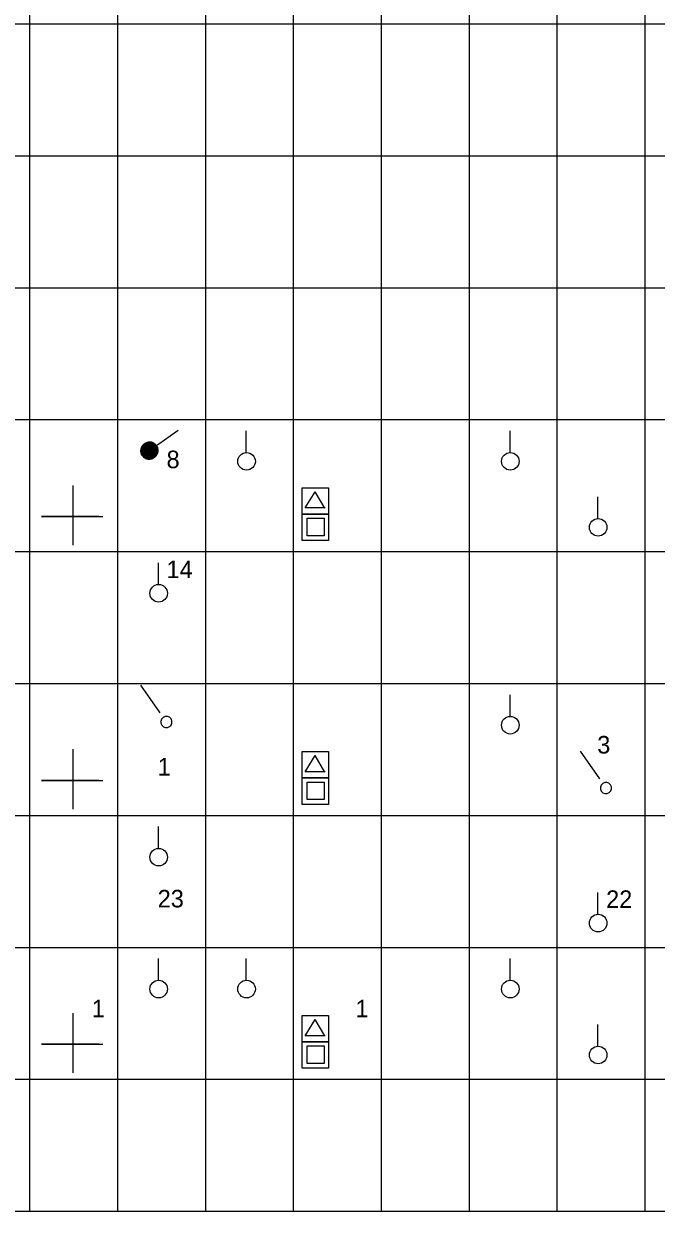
# Model space of a CAD drawing. Extents: x -28 to 822, y 61 to 665.
# Drawn here: x 192.5 to 264.4, y 111.7 to 246.8 of the extents above; entities that cross this region are included whole.
import ezdxf

# ---------------------------------------------------------------- set-up
doc = ezdxf.new("R2010")
doc.units = 0

# ---------------------------------------------------------------- blocks, each defined once
blk = doc.blocks.new('_X10')
for p, q in [((370.45, 480.11), (371.52, 481.17)), ((370.45, 480.13), (371.5, 481.17)), ((370.45, 480.14), (371.48, 481.17)), ((370.45, 480.16), (371.46, 481.17)), ((370.45, 480.18), (371.45, 481.17)), ((370.45, 480.2), (371.43, 481.17)), ((370.45, 480.21), (371.41, 481.17)), ((370.45, 480.23), (371.39, 481.17)), ((370.46, 480.06), (371.56, 481.17)), ((370.46, 480.08), (371.55, 481.17)), ((370.46, 480.09), (371.53, 481.17)), ((370.46, 480.25), (371.37, 481.17)), ((370.46, 480.27), (371.35, 481.17)), ((370.46, 480.29), (371.33, 481.17)), ((370.46, 480.01), (371.61, 481.16)), ((370.46, 480.03), (371.6, 481.16)), ((370.46, 480.04), (371.58, 481.16)), ((370.46, 480.31), (371.31, 481.16)), ((370.46, 480.33), (371.29, 481.16)), ((370.47, 480), (371.63, 481.16)), ((370.47, 480.35), (371.27, 481.16)), ((370.47, 479.97), (371.66, 481.15)), ((370.47, 479.98), (371.64, 481.15)), ((370.47, 480.37), (371.25, 481.15)), ((370.48, 479.95), (371.67, 481.15)), ((370.48, 480.4), (371.23, 481.15)), ((370.48, 479.93), (371.7, 481.14)), ((370.48, 479.94), (371.68, 481.14)), ((370.48, 480.42), (371.2, 481.14)), ((370.49, 479.91), (371.71, 481.14)), ((370.49, 479.88), (371.74, 481.13)), ((370.49, 479.9), (371.73, 481.13)), ((370.49, 480.45), (371.18, 481.13)), ((370.5, 479.87), (371.75, 481.13)), ((370.5, 480.47), (371.15, 481.13)), ((370.5, 479.86), (371.77, 481.12)), ((370.51, 479.84), (371.78, 481.12)), ((370.51, 480.5), (371.13, 481.12)), ((370.51, 479.83), (371.79, 481.11)), ((370.52, 479.82), (371.81, 481.11)), ((370.52, 480.52), (371.1, 481.11)), ((370.52, 479.81), (371.82, 481.1)), ((370.53, 479.79), (371.83, 481.1)), ((370.53, 480.55), (371.07, 481.1)), ((370.53, 479.78), (371.84, 481.09)), ((370.54, 479.77), (371.86, 481.09)), ((370.54, 479.76), (371.87, 481.08)), ((370.54, 480.58), (371.04, 481.08)), ((370.55, 479.74), (371.88, 481.08)), ((370.55, 479.73), (371.89, 481.07)), ((370.56, 480.62), (371.01, 481.07)), ((370.56, 479.72), (371.9, 481.06)), ((370.57, 479.71), (371.92, 481.06)), ((370.57, 479.7), (371.93, 481.05)), ((370.58, 479.69), (371.94, 481.05)), ((370.58, 480.66), (370.97, 481.05)), ((370.59, 479.67), (371.95, 481.04)), ((370.59, 479.66), (371.96, 481.03)), ((370.6, 479.65), (371.97, 481.03)), ((370.6, 479.64), (371.98, 481.02)), ((370.6, 480.7), (370.93, 481.02)), ((370.61, 479.63), (371.99, 481.01)), ((370.62, 479.62), (372, 481.01)), ((370.63, 479.61), (372.02, 481)), ((370.63, 479.6), (372.03, 480.99)), ((370.64, 480.75), (370.87, 480.99)), ((370.64, 479.59), (372.04, 480.98)), ((370.65, 479.58), (372.05, 480.98)), ((370.66, 479.57), (372.06, 480.97)), ((370.66, 479.56), (372.07, 480.96)), ((370.67, 479.55), (372.08, 480.95)), ((370.68, 479.54), (372.09, 480.95)), ((370.69, 479.53), (372.1, 480.94)), ((370.7, 479.52), (372.11, 480.93)), ((370.7, 479.51), (372.11, 480.92)), ((370.71, 480.84), (370.79, 480.92)), ((370.71, 479.5), (372.12, 480.91)), ((370.72, 479.49), (372.13, 480.9)), ((370.73, 479.48), (372.14, 480.9)), ((370.74, 479.47), (372.15, 480.89)), ((370.75, 479.46), (372.16, 480.88)), ((370.76, 479.46), (372.17, 480.87)), ((370.76, 479.45), (372.18, 480.86)), ((370.77, 479.44), (372.19, 480.85)), ((370.78, 479.43), (372.19, 480.84)), ((370.79, 479.42), (372.2, 480.83)), ((370.8, 479.41), (372.21, 480.82)), ((370.81, 479.4), (372.22, 480.81)), ((370.82, 479.4), (372.23, 480.8)), ((370.83, 479.39), (372.24, 480.79)), ((370.84, 479.38), (372.24, 480.78)), ((370.85, 479.37), (372.25, 480.77)), ((370.86, 479.37), (372.26, 480.76)), ((370.87, 479.36), (372.27, 480.75)), ((370.88, 479.35), (372.27, 480.74)), ((370.89, 479.34), (372.28, 480.73)), ((370.9, 479.34), (372.29, 480.72)), ((370.91, 479.33), (372.29, 480.71)), ((370.92, 479.32), (372.3, 480.7)), ((370.93, 479.32), (372.31, 480.69)), ((370.95, 479.31), (372.31, 480.68)), ((370.96, 479.3), (372.32, 480.67)), ((370.97, 479.3), (372.33, 480.66)), ((370.98, 479.29), (372.33, 480.64)), ((370.99, 479.28), (372.34, 480.63)), ((371, 479.28), (372.35, 480.62)), ((371.01, 479.27), (372.35, 480.61)), ((371.03, 479.27), (372.36, 480.6)), ((371.04, 479.26), (372.36, 480.59)), ((371.05, 479.26), (372.37, 480.57)), ((371.06, 479.25), (372.37, 480.56)), ((371.08, 479.25), (372.38, 480.55)), ((371.09, 479.24), (372.38, 480.54)), ((371.1, 479.24), (372.39, 480.52)), ((371.11, 479.23), (372.39, 480.51)), ((371.13, 479.23), (372.4, 480.5)), ((371.14, 479.22), (372.4, 480.48)), ((371.15, 479.22), (372.41, 480.47)), ((371.17, 479.21), (372.41, 480.46)), ((371.18, 479.21), (372.41, 480.44)), ((371.2, 479.21), (372.42, 480.43)), ((371.21, 479.2), (372.42, 480.42)), ((371.22, 479.2), (372.43, 480.4)), ((371.24, 479.2), (372.43, 480.39)), ((371.25, 479.19), (372.43, 480.37)), ((371.27, 479.19), (372.43, 480.36)), ((371.28, 479.19), (372.44, 480.34)), ((371.3, 479.18), (372.44, 480.33)), ((371.31, 479.18), (372.44, 480.31)), ((371.33, 479.18), (372.44, 480.3)), ((371.34, 479.18), (372.45, 480.28)), ((371.36, 479.18), (372.45, 480.26)), ((371.38, 479.17), (372.45, 480.25)), ((371.39, 479.17), (372.45, 480.23)), ((371.41, 479.17), (372.45, 480.21)), ((371.43, 479.17), (372.45, 480.2)), ((371.44, 479.17), (372.45, 480.18)), ((371.46, 479.17), (372.45, 480.16)), ((371.48, 479.17), (372.45, 480.14)), ((371.5, 479.17), (372.45, 480.13)), ((371.52, 479.17), (372.45, 480.11)), ((371.54, 479.18), (372.45, 480.09)), ((371.56, 479.18), (372.45, 480.07)), ((371.58, 479.18), (372.44, 480.05)), ((371.6, 479.18), (372.44, 480.03)), ((371.62, 479.19), (372.44, 480.01)), ((371.64, 479.19), (372.43, 479.99)), ((371.66, 479.19), (372.43, 479.96)), ((371.68, 479.2), (372.42, 479.94)), ((371.71, 479.21), (372.42, 479.92)), ((371.73, 479.21), (372.41, 479.89)), ((371.76, 479.22), (372.4, 479.87)), ((371.78, 479.23), (372.4, 479.84)), ((371.81, 479.24), (372.39, 479.81)), ((371.84, 479.25), (372.37, 479.78)), ((371.87, 479.27), (372.36, 479.75)), ((371.91, 479.28), (372.34, 479.72)), ((371.95, 479.3), (372.32, 479.68)), ((371.99, 479.33), (372.29, 479.63)), ((372.05, 479.37), (372.26, 479.58))]:
    blk.add_line(p, q)

msp = doc.modelspace()

# ---------------------------------------------------------------- linework, layer by layer
for p, q in [((193.12, 381.74), (193.12, 111.74)), ((203.12, 381.74), (203.12, 111.74)), ((213.12, 381.74), (213.12, 111.74)), ((223.12, 381.74), (223.12, 111.74)), ((233.12, 381.74), (233.12, 111.74)), ((243.12, 381.74), (243.12, 111.74)), ((253.12, 381.74), (253.12, 111.74)), ((263.12, 381.74), (263.12, 111.74)), ((5.07, 246.74), (540.62, 246.74)), ((5.07, 246.74), (540.62, 246.74)), ((5.07, 231.74), (292.72, 231.74)), ((5.07, 216.74), (540.62, 216.74)), ((5.07, 201.74), (540.62, 201.74)), ((5.07, 201.74), (540.62, 201.74)), ((5.07, 201.74), (540.62, 201.74)), ((54.09, 201.74), (540.62, 201.74)), ((207.57, 198.8), (210.02, 200.53)), ((217.78, 197.94), (217.78, 200.47)), ((247.78, 197.94), (247.78, 200.47)), ((198.04, 194.27), (198.04, 187.47)), ((224.46, 191.7), (225.62, 193.55)), ((226.73, 191.67), (225.62, 193.55)), ((257.78, 190.44), (257.78, 192.97)), ((226.74, 191.7), (224.46, 191.7)), ((5.07, 186.74), (295.62, 186.74)), ((207.78, 182.94), (207.78, 185.47)), ((5.07, 171.74), (540.62, 171.74)), ((205.76, 171.56), (207.96, 168.41)), ((247.78, 167.94), (247.78, 170.47)), ((198.04, 164.27), (198.04, 157.47)), ((224.46, 161.7), (225.62, 163.55)), ((226.73, 161.67), (225.62, 163.55)), ((255.76, 164.06), (257.96, 160.91)), ((226.74, 161.7), (224.46, 161.7)), ((5.07, 156.74), (295.62, 156.74)), ((207.78, 152.94), (207.78, 155.47)), ((257.78, 145.44), (257.78, 147.97)), ((5.07, 141.74), (540.62, 141.74)), ((207.78, 137.94), (207.78, 140.47)), ((217.78, 137.94), (217.78, 140.47)), ((247.78, 137.94), (247.78, 140.47)), ((198.04, 134.27), (198.04, 127.47)), ((224.46, 131.7), (225.62, 133.55)), ((226.73, 131.67), (225.62, 133.55)), ((257.78, 130.44), (257.78, 132.97)), ((226.74, 131.7), (224.46, 131.7)), ((5.07, 126.74), (293.12, 126.74)), ((5.07, 111.74), (540.62, 111.74))]:
    msp.add_line(p, q)
for points in [[(227.14, 191), (224.14, 191), (224.14, 194), (227.14, 194)], [(227.14, 188), (224.14, 188), (224.14, 191), (227.14, 191)], [(226.62, 188.54), (224.69, 188.54), (224.69, 190.54), (226.62, 190.54)], [(227.14, 161), (224.14, 161), (224.14, 164), (227.14, 164)], [(227.14, 158), (224.14, 158), (224.14, 161), (227.14, 161)], [(226.62, 158.54), (224.69, 158.54), (224.69, 160.54), (226.62, 160.54)], [(227.14, 131), (224.14, 131), (224.14, 134), (227.14, 134)], [(227.14, 128), (224.14, 128), (224.14, 131), (227.14, 131)], [(226.62, 128.54), (224.69, 128.54), (224.69, 130.54), (226.62, 130.54)]]:
    msp.add_lwpolyline(points, close=True)
for points in [[(195.44, 190.72), (201.04, 190.72), (194.5, 190.72), (201.46, 190.72)], [(195.44, 160.72), (201.04, 160.72), (194.5, 160.72), (201.46, 160.72)], [(195.44, 130.72), (201.04, 130.72), (194.5, 130.72), (201.46, 130.72)]]:
    msp.add_lwpolyline(points)
for centre in [(217.81, 197), (247.81, 197), (257.81, 189.5), (207.81, 182), (247.81, 167), (207.81, 152), (257.81, 144.5), (207.81, 137), (217.81, 137), (247.81, 137), (257.81, 129.5)]:
    msp.add_circle(centre, 1)
for centre, start, end in [((208.69, 167.36), 35, 215), ((208.69, 167.36), 215, 35), ((258.69, 159.86), 35, 215), ((258.69, 159.86), 215, 35)]:
    msp.add_arc(centre, 0.64, start, end)

# ---------------------------------------------------------------- block references
at = {"rotation": -92.29148628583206}
msp.add_blockref('_X10', (-258.18, 588.57), dxfattribs=at)

# ---------------------------------------------------------------- texts
for s, p in [('8', (208.71, 196.22)), ('14', (208.71, 183.72)), ('3', (257.7, 163.78)), ('1', (207.7, 161.28)), ('23', (207.7, 146.28)), ('22', (258.71, 146.22)), ('1', (200.2, 133.78)), ('1', (230.2, 133.78))]:
    msp.add_text(s, height=2).set_placement(p)

doc.saveas('drawing.dxf')
